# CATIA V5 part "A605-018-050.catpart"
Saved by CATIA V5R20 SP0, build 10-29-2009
Part number: A605-018-050
Source: Unknown
Property "A": "0.000"
Property "ARTICLENO": "A605-018-050"
Property "BOMINFO": "A605-018-050"
Property "CODE": "A605-018-050"
Property "D": "6.500"
Property "FORM": "A"
Property "L": "50.000"
Property "L1": "20.000"
Property "LINA": "A605-018-050"
Property "NB": "A605-018-050"
Property "NBSYN": "$CODE."
Property "NN": "A605"
Property "NT": "Wear Plates, self-lubricating"
Property "SCREW": "2*M6X10"
Property "SUPPLIER": "CF"
Property "W": "18.000"
Bounding box of the stored display mesh (mm): x -18 to 0, y 0 to 5, z -50 to 0
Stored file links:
  C:\Users\Utente\Desktop\3D files A605\A605-018-050.catpart
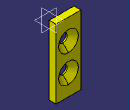
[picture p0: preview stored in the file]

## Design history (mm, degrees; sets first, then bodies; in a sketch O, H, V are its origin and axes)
Body1 "Geometry.1" (main body)
  Solid1 "A605-018-050.catpart": solid without history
